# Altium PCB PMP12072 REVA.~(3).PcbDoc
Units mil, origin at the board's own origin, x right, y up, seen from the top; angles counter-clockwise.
Board outline 4950 x 3450 mil, 2 copper layers (Top Layer, Bottom Layer), stack 62 mil thick; 23 components, 0 nets, 11 pads, 0 vias.
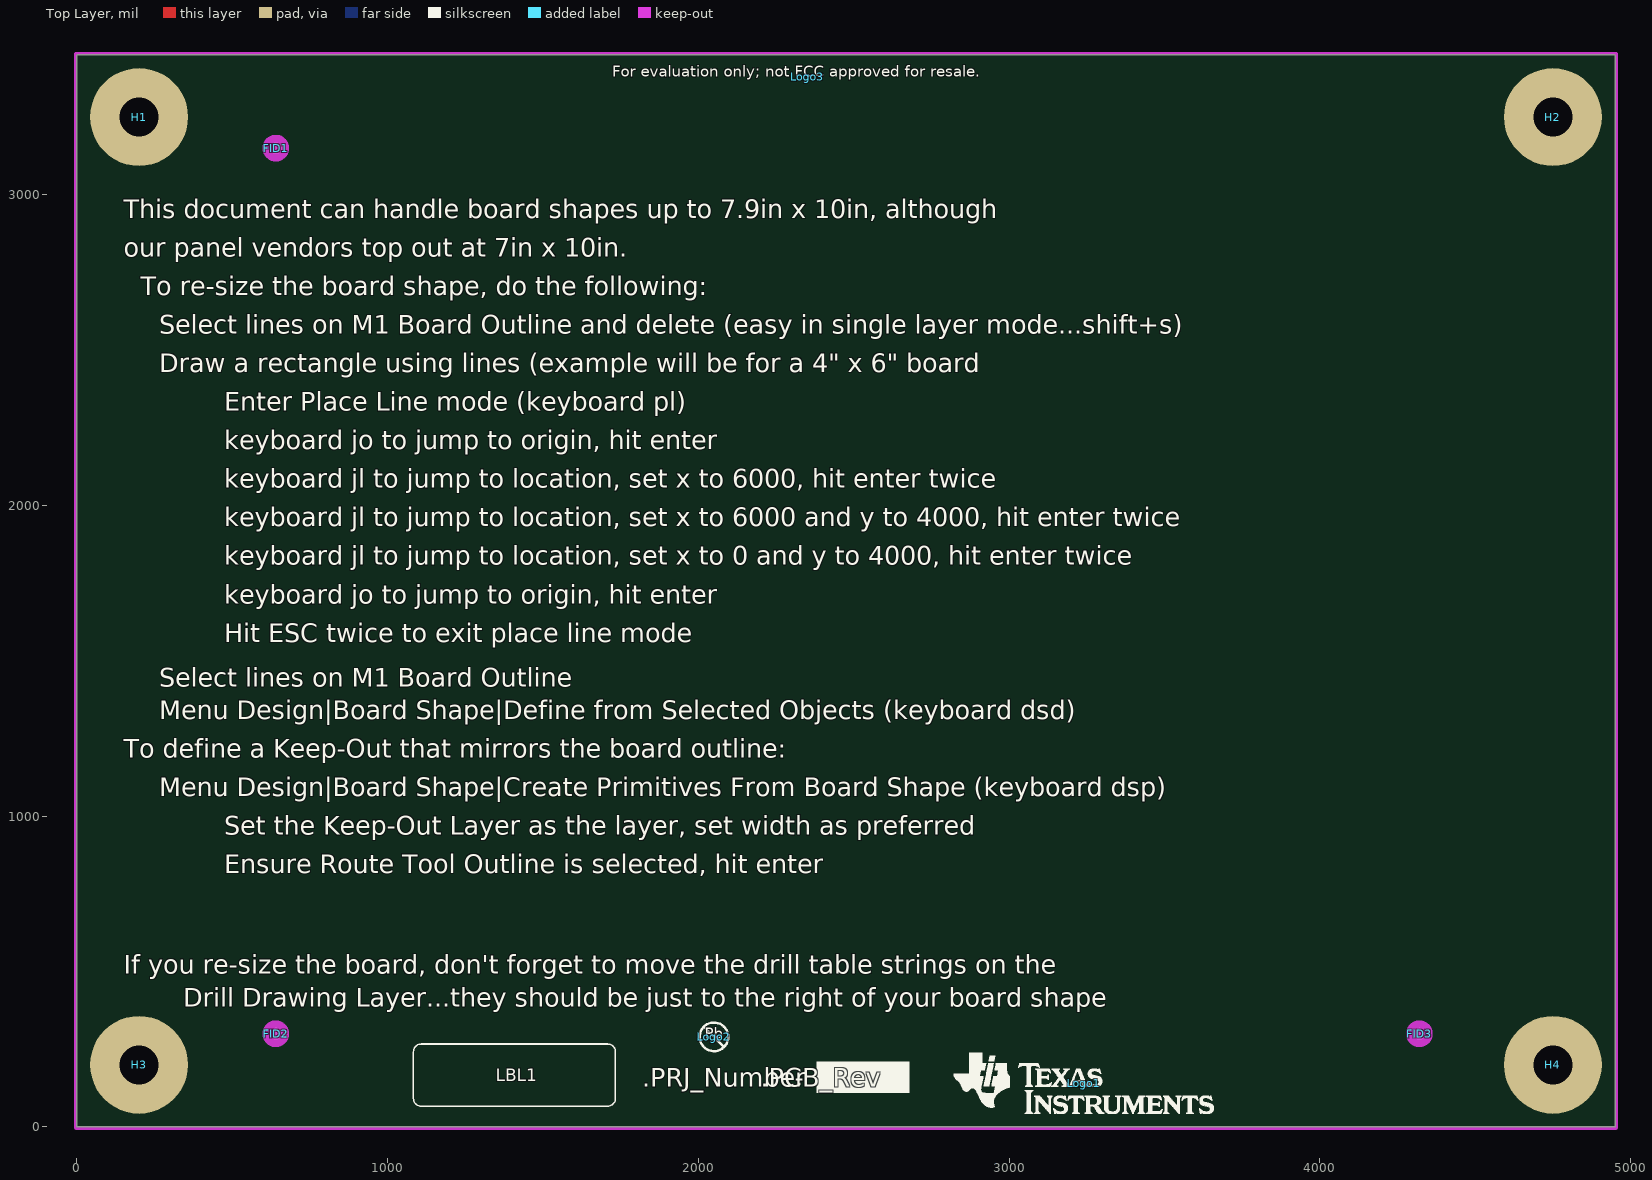
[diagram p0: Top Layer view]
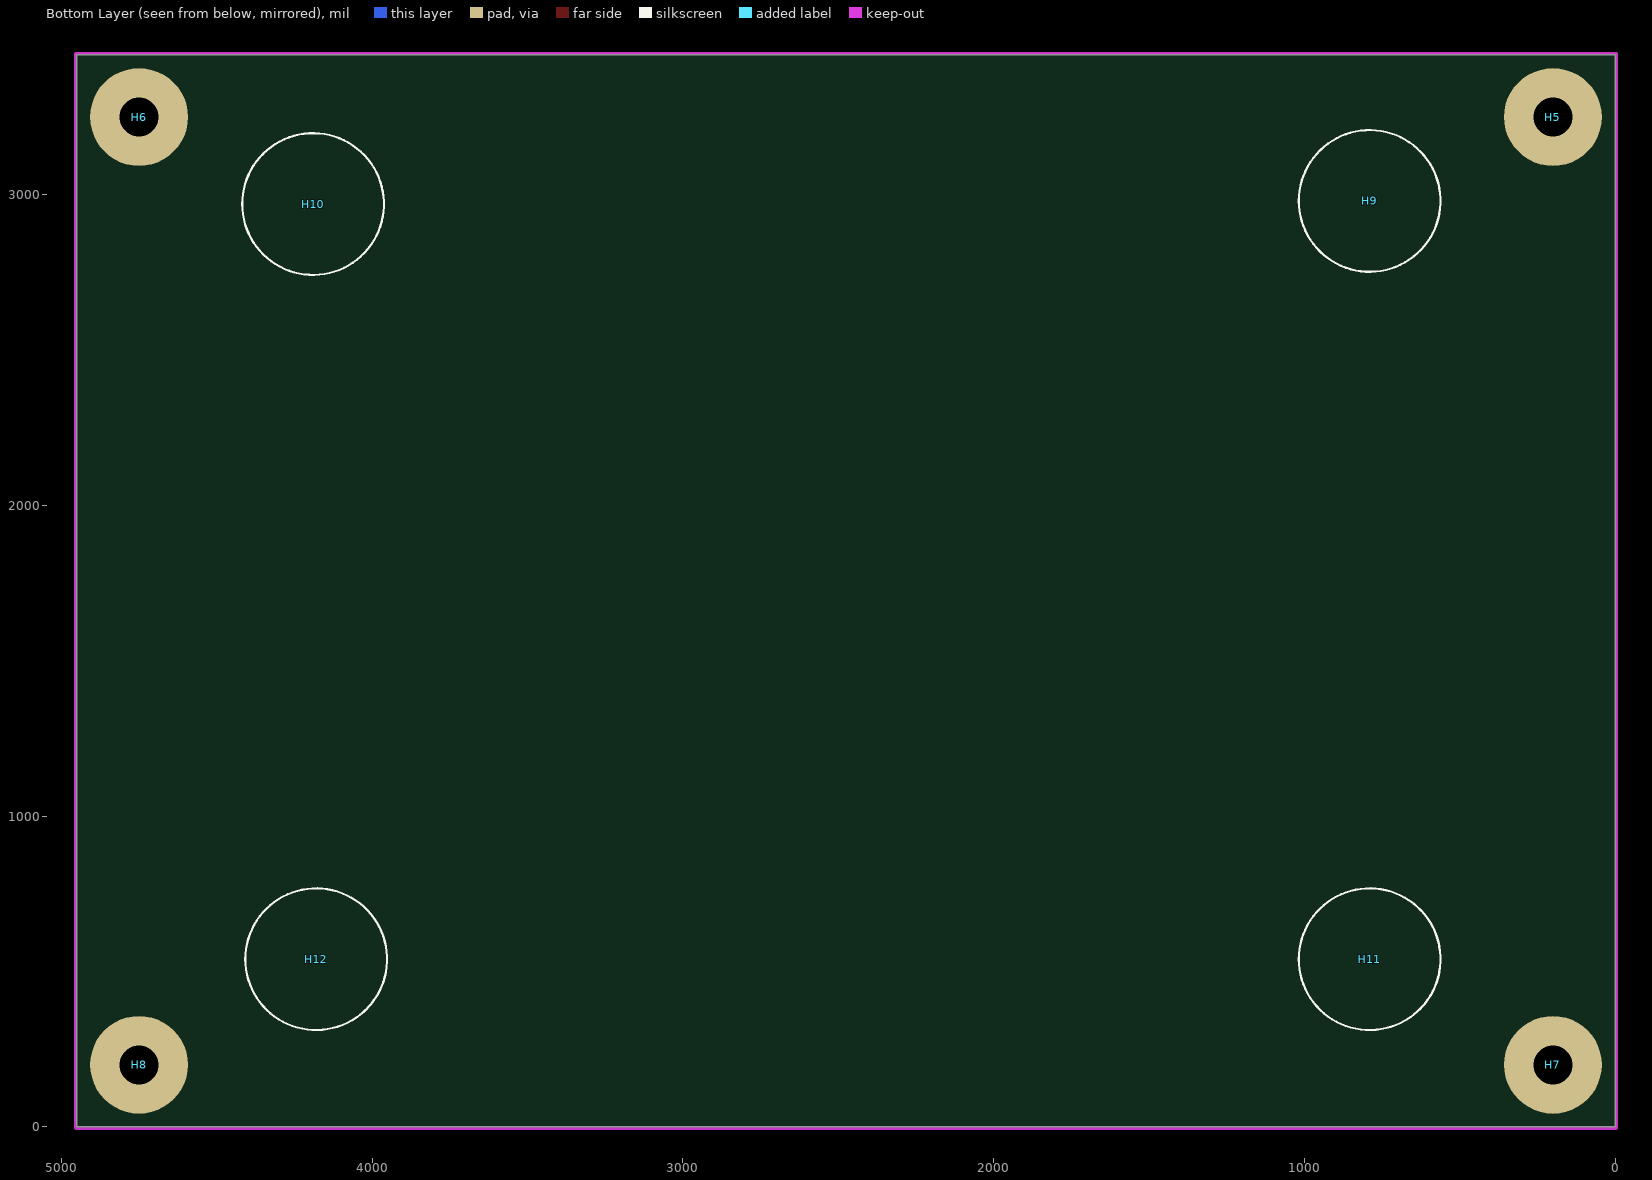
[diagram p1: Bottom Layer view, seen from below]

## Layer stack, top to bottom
Top Solder: solder mask 0.4, Solder Resist, Dk 3.5
Top Layer: signal copper 1.4
Dielectric1: core 59.2, FR-4, Dk 4.8
Bottom Layer: signal copper 1.4
Bottom Solder: solder mask 0.4, Solder Resist, Dk 3.5

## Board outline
0,0 4950,0 4950,3450 0,3450

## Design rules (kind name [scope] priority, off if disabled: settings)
AcuteAngle [All] p1: minimum=4.50000000000000E+0001 checktracksonly=FALSE
AssemblyTestPointUsage [All] p1: valid=2
Clearance Clearance_Keepouts [((IsTrack Or IsArc) And Not InPoly) And IsFree and IsKeepOut vs ((IsTrack Or IsArc) And Not InPoly) And IsFree and IsKeepOut] p1: gap=0
Clearance Clearance_BoardEdge_MountingHoles [OnCopper and InComponentClass('Mounting Holes') vs IsKeepOut] p2: gap=40
Clearance Clearance_BoardEdge_Poly [OnCopper and InPoly vs IsKeepOut] p3: gap=25
Clearance Clearance_BoardEdge [OnCopper and Not InComponentClass('Logo') and not InComponentClass('FiducialMark') and not InRegion(1000,500,4000,800) and Not IsKeepout vs IsKeepOut] p4: gap=75
Clearance Clearance_Poly [InPolygon] p5: gap=25
Clearance [All] p6: gap=7.87
ComponentClearance ComponentClearance_MountingHoles_FiducialMarks [InComponentClass('Mounting Holes') vs InComponentClass('FiducialMark')] p1: gap=50 collisioncheckmode=3 verticalgap=10 showdistances=FALSE
ComponentClearance ComponentClearance_Shunt [InComponentClass('Header') vs InComponentClass('Shunt')] p2: gap=0 collisioncheckmode=3 verticalgap=0 showdistances=FALSE
ComponentClearance ComponentClearance_Logo [InComponentClass('Logo')] p3: gap=50 collisioncheckmode=3 verticalgap=10 showdistances=FALSE
ComponentClearance ComponentClearance_ScrewToNut [(HasFootprint('NY PMS 440 0025 PH')) vs (HasFootprint('Keystone_1902C'))] p4: gap=5 collisioncheckmode=3 verticalgap=10 showdistances=FALSE
ComponentClearance ComponentClearance_MountingHoles [InComponentClass('Mounting Holes')] p5: gap=250 collisioncheckmode=3 verticalgap=100000 showdistances=FALSE
ComponentClearance ComponentClearance_SmallPassives [HasFootprint('0201*') or HasFootprint('0402*') or HasFootprint('0508') or HasFootprint('0603*') or HasFootprint('0612') or HasFootprint('0805*') or HasFootprint('0815*') or HasFootprint('0830*') or HasFootprint('1206*') or HasFootprint('1210*') or HasFootprint('1808*') or HasFootprint('1812*') or HasFootprint('1825*') or HasFootprint('2010*') or HasFootprint('2220*') or HasFootprint('2225*') or HasFootprint('2512*') or HasFootprint('2728*') or HasFootprint('3518*') vs HasFootprint('0201*') or HasFootprint('0402*') or HasFootprint('0508') or HasFootprint('0603*') or HasFootprint('0612') or HasFootprint('0805*') or HasFootprint('0815*') or HasFootprint('0830*') or HasFootprint('1206*') or HasFootprint('1210*') or HasFootprint('1808*') or HasFootprint('1812*') or HasFootprint('1825*') or HasFootprint('2010*') or HasFootprint('2220*') or HasFootprint('2225*') or HasFootprint('2512*') or HasFootprint('2728*') or HasFootprint('3518*')] p6: gap=20 collisioncheckmode=3 verticalgap=10 showdistances=FALSE
ComponentClearance ComponentClearance_THtoSMT [IsThruComponent vs IsSMTComponent] p7: gap=100 collisioncheckmode=3 verticalgap=30 showdistances=FALSE
ComponentClearance ComponentClearance_THtoTH [IsThruComponent vs IsThruComponent] p8: gap=118.11 collisioncheckmode=3 verticalgap=30 showdistances=FALSE
ComponentClearance [All] p9: gap=40 collisioncheckmode=3 verticalgap=10 showdistances=FALSE
DiffPairsRouting [All] p1: maxlimit=100 minlimit=10 mostfreqgap=10 toplayer_minwidth=15 toplayer_maxwidth=15 toplayer_prefwidth=15 bottomlayer_minwidth=15 bottomlayer_maxwidth=15 bottomlayer_prefwidth=15 maxuncoupledlength=1000
FabricationTestPointUsage TestPointUsage [All] p1: valid=2 allowmultiple=FALSE
FabricationTestpoint Testpoint [All] p1: side=3 testpointundercomponent=TRUE minsize=40 maxsize=100 preferedsize=60 minholesize=0 maxholesize=40 preferedholesize=32 testpointgrid=1 allowsidetop=TRUE allowsidebottom=TRUE usegrid=TRUE gridtolerance=0.01
FanoutControl Fanout_LCC [IsLCC] p1: bgadir=Out bgaviamode=Centered fanoutstyle=Auto fanoutdirection=Alternating viagrid=1 // Fanout_LCC (Default Rule)
FanoutControl Fanout_BGA [IsBGA] p2: bgadir=Out bgaviamode=Centered fanoutstyle=Auto fanoutdirection=Alternating viagrid=1 // Fanout_BGA (Default Rule)
FanoutControl Fanout_Default [All] p4: bgadir=Out bgaviamode=Centered fanoutstyle=Auto fanoutdirection=Alternating viagrid=1 // Fanout_Default (Default Rule)
FanoutControl Fanout_Small [(CompPinCount < 5)] p5: bgadir=Out bgaviamode=Centered fanoutstyle=Auto fanoutdirection=OutThenIn viagrid=1 // Fanout_Small (Default Rule)
HoleSize [All] p1: absolutevalues=TRUE maxlimit=251 minlimit=8 maxpercent=80.000 minpercent=20.000
MinimumAnnularRing MinimumAnnularRing_ThermalPadVias [IsVia and InAnyComponent] p1: minimumring=5.91
MinimumAnnularRing [All] p2: minimumring=9
MinimumSolderMaskSliver MinimumSolderMaskSliver_Logo [InComponentClass('Logo') vs InComponentClass('Logo')] p1: minsoldermaskwidth=0.7
MinimumSolderMaskSliver [All] p2: minsoldermaskwidth=3.94
PlaneConnect [All] p1: planeconnectstyle=Relief reliefexpansion=10 reliefentries=4 reliefconductorwidth=10 reliefairgap=10
PolygonConnect [All] p1: connectstyle=Relief reliefconductorwidth=10 reliefentries=4 polygonreliefangle="90 Angle" airgapwidth=10
RoutingVias ThermalPadVias [IsVia and InAnyComponent] p1: holewidth=7.87 width=19.68 viastyle="Through Hole" minholewidth=7.87 minwidth=19.68 maxholewidth=12.99 maxwidth=23.62
RoutingVias [All] p2: holewidth=16 width=34 viastyle="Through Hole" minholewidth=7.87 minwidth=26 maxholewidth=40 maxwidth=65
SilkToBoardRegionClearance [Not ((IsComment or IsDesignator) And (Hide <> 'False')) and not InRegion(1000,500,4000,800)] p1:
SilkToSilkClearance SilkToSilkClearance_Pb-FreeLogo [(HasFootprint('Pb-Free_Overlay_Medium') OR HasFootprint('Pb-Free_Overlay_Small')) vs (HasFootprint('Pb-Free_Overlay_Medium') OR HasFootprint('Pb-Free_Overlay_Small'))] p1: silktosilkclearance=0
SilkToSilkClearance [All] p2: silktosilkclearance=4
SilkToSolderMaskClearance SilkToComonentPadClearance [IsPad and InAnycomponent] p1: minsilkscreentomaskgap=5 clearancetoexposedcopper=TRUE
SilkToSolderMaskClearance "Silk to Solder Mask Opening" [All] p2: minsilkscreentomaskgap=4 clearancetoexposedcopper=FALSE
SolderMaskExpansion [All] p1: expansion=1.97
UnpouredPolygon [All] p1: allowunpoured=FALSE
Width [All] p1: maxlimit=100 minlimit=6 preferedwidth=10 checkconnectedcopper=TRUE
14 further rules are at their usual default settings.

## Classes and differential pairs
component class Label: LBL1
component class AssemblyNote: ZZ1 ZZ2 ZZ3 ZZ4
component class FiducialMark: FID1 FID2 FID3
component class Logo: Logo1
component class "Mounting Holes": H1 H2 H3 H4

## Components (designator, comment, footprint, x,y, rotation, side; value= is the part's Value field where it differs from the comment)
FID1 "Fiducial" Fiducial10-20 640,3150 r0 top
FID2 "Fiducial" Fiducial10-20 640,300 r0 top
FID3 "Fiducial" Fiducial10-20 4320,300 r0 top
H1 "NY PMS 440 0025 PH" "NY PMS 440 0025 PH" 200,3250 r0 top locked
H2 "NY PMS 440 0025 PH" "NY PMS 440 0025 PH" 4750,3250 r0 top locked
H3 "NY PMS 440 0025 PH" "NY PMS 440 0025 PH" 200,200 r0 top locked
H4 "NY PMS 440 0025 PH" "NY PMS 440 0025 PH" 4750,200 r0 top locked
H5 "1902C" Keystone_1902C 200,3250 r180 bottom locked
H6 "1902C" Keystone_1902C 4750,3250 r180 bottom locked
H7 "1902C" Keystone_1902C 200,200 r180 bottom locked
H8 "1902C" Keystone_1902C 4750,200 r180 bottom locked
H9 "SJ-5303 (CLEAR)" Bumpon_SJ5003Transparent 790,2980 r180 bottom
H10 "SJ-5303 (CLEAR)" Bumpon_SJ5003Transparent 4190,2970 r180 bottom
H11 "SJ-5303 (CLEAR)" Bumpon_SJ5003Transparent 790,540 r180 bottom
H12 "SJ-5303 (CLEAR)" Bumpon_SJ5003Transparent 4180,540 r180 bottom
LBL1 "Size: 0.65\" x 0.20 \"" Label_650x200 1408,167 r0 top
Logo1 "Texas Instruments" TI_Stacked_Overlay_Small 3240,140 r0 top
Logo2 "Pb-Free Symbol" Pb-Free_Overlay_Small 2050,290 r0 top
Logo3 "FCC disclaimer" FCC_disclaimer 2350,3380 r0 top
ZZ1 "This Assembly Note is for PCB labels only" AssemblyNoteLabel 185,3938 r0 top
ZZ2 "These assemblies are ESD sensitive, ESD precautions shall be observed." AssemblyNote 185,3829.11 r0 top
ZZ3 "These assemblies must be clean and free from flux and all contaminants. Use of no clean flux is not acceptable." AssemblyNote 185,3740.56 r0 top
ZZ4 "These assemblies must comply with workmanship standards IPC-A-610 Class 2, unless otherwise specified." AssemblyNote 185,3652 r0 top

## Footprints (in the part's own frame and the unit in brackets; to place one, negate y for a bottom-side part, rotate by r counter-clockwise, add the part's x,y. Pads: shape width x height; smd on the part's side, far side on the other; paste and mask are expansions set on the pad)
AssemblyNote [mil] "Assembly Note"
AssemblyNoteLabel [mil] "Assembly Note for PCB Labels"
Bumpon_SJ5003Transparent [mil] "3M Hemispherical Bumpon transparent"
  round 1 on Mech4: 0(0,0)
  silkscreen extent -228,-228 228,228, body extent -217,-218 219,218, height 197
FCC_disclaimer [mil]
Fiducial10-20 [mm]
  round 1 smd mask+0.5: 1(0,0)
  Top Layer keep-out circle w1.178: c0,0 r0.5
Keystone_1902C [mil] "Hex Standoff, 4-40 threaded, nylon"
  body extent -145,-126 146,126, height 501
Label_650x200 [mil] "Thermal Transfer Label"
  silkscreen extent -325,-100 325,100, body extent -326,-101 326,101, height 1
"NY PMS 440 0025 PH" [mm] "4-40 nylon screw and mounting hole"
  round 8 hole 3.2: 1(0,0)
  body extent -3.3,-3.3 3.3,3.3, height 2.69
Pb-Free_Overlay_Small [mil]
  silkscreen extent -46,-46 46,46
TI_Stacked_Overlay_Small [mil]
  silkscreen extent -418,-98 418,98

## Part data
FID1 FID2 FID3: "Fiducial mark.  There is nothing to buy or mount."
H1 H2 H3 H4: "Machine Screw, Round, #4-40 x 1/4, Nylon, Philips panhead"
H5 H6 H7 H8: "Standoff, Hex, 0.5\"L #4-40 Nylon"
H9 H10 H11 H12: "Bumpon, Hemisphere, 0.44 X 0.20, Clear"
LBL1: library part THT-14-423-10, "Thermal Transfer Printable Labels, 0.650\" W x 0.200\" H - 10,000 per roll"
Logo1: library part TI_Logo, "Texas Instrument Corporate Signature"
Logo2: library part Pb-Free
Logo3: library part FCC_disclaimer, "FCC_disclaimer"
ZZ1: library part AssemblyNoteLabel
ZZ2 ZZ3 ZZ4: library part AssemblyNote

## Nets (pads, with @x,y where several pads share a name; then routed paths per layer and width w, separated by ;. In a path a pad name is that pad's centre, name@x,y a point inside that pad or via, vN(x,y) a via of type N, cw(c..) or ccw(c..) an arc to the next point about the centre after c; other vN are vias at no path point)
pads on no net: FID1.1 FID2.1 FID3.1 H1.1 H2.1 H3.1 H4.1 H9.0 H10.0 H11.0 H12.0

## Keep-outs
Keep-Out Layer:
  lines w10: -5,0 ccw(c0,0) 0,-5 ; -5,0 ccw(c0,0) 0,-5 ; -5,0 -5,3450 ; -5,3450 cw(c0,3450) 0,3455 ; -5,3450 cw(c0,3450) 0,3455 ; 0,-5 4950,-5 ; 0,3455 4950,3455 ; 4950,-5 ccw(c4950,0) 4955,0 ; 4950,-5 ccw(c4950,0) 4955,0 ; 4950,3455 cw(c4950,3450) 4955,3450 ; 4950,3455 cw(c4950,3450) 4955,3450 ; 4955,0 4955,3450
  text ".Layer_Name" at 577,-858.49 h60

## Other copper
Top Layer:
  text ".Layer_Name" at 577,-858.49 h60
Bottom Layer:
  text ".Layer_Name" at 577,-858.49 h60

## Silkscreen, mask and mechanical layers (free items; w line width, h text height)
Top Overlay:
  region: 2680,210 2380,210 2380,110 2680,110
  text "This document can handle board shapes up to 7.9in x 10in, although" at 150,2925 h60
  text "our panel vendors top out at 7in x 10in." at 150,2800.94 h60
  text "To re-size the board shape, do the following:" at 205,2676.88 h60
  text "Select lines on M1 Board Outline and delete (easy in single layer mode...shift+s)" at 265,2552.82 h60
  text "Draw a rectangle using lines (example will be for a 4\" x 6\" board" at 265,2428.76 h60
  text "Enter Place Line mode (keyboard pl)" at 475,2304.71 h60
  text "keyboard jo to jump to origin, hit enter" at 475,2180.65 h60
  text "keyboard jl to jump to location, set x to 6000, hit enter twice" at 475,2056.59 h60
  text "keyboard jl to jump to location, set x to 6000 and y to 4000, hit enter twice" at 475,1932.53 h60
  text "keyboard jl to jump to location, set x to 0 and y to 4000, hit enter twice" at 475,1808.47 h60
  text "keyboard jo to jump to origin, hit enter" at 475,1684.41 h60
  text "Hit ESC twice to exit place line mode" at 475,1560.35 h60
  text "Select lines on M1 Board Outline" at 265,1416.3 h60
  text "Menu Design|Board Shape|Define from Selected Objects (keyboard dsd)" at 265,1312.24 h60
  text "To define a Keep-Out that mirrors the board outline:" at 150,1188.18 h60
  text "Menu Design|Board Shape|Create Primitives From Board Shape (keyboard dsp)" at 265,1064.12 h60
  text "Set the Keep-Out Layer as the layer, set width as preferred" at 475,940.06 h60
  text "Ensure Route Tool Outline is selected, hit enter" at 475,816 h60
  text "If you re-size the board, don't forget to move the drill table strings on the" at 150,493 h60
  text "Drill Drawing Layer...they should be just to the right of your board shape" at 343,387 h60
  text ".PRJ_Number" at 1820,130.01 h60
  text ".PCB_Rev" at 2200,130.01 h60
  text "-" at 2310,130.01 h60
  text ".Layer_Name" at 577,-858.49 h60
Bottom Overlay:
  text ".Layer_Name" at 577,-858.49 h60
Top Paste:
  text ".Layer_Name" at 577,-858.49 h60
Bottom Paste:
  text ".Layer_Name" at 577,-858.49 h60
Top Solder:
  text ".Layer_Name" at 577,-858.49 h60
  text ".Layer_Name" at 577,-858.49 h60
Bottom Solder:
  text ".Layer_Name" at 577,-858.49 h60
Drill Guide:
  text ".Layer_Name" at 577,-858.49 h60
M1 Board Outline:
  the board outline again, w10
  text ".Layer_Name" at 577,-858.49 h60
M2 Board Dimensions:
  rectangle: 125,-400 500,-275
  rectangle: 0,-275 125,-150
  lines w7: 0,-275 1000,-275 ; 125,-400 125,-150 ; 250,-400 250,-150 ; 500,-400 500,-150 ; 750,-400 750,-150 ; 0,-400 0,-150 1000,-150 1000,-400 0,-400
  text ".Layer_Name" at 577,-858.49 h60
M3 3D STEP Top:
  text ".Layer_Name" at 577,-858.49 h60
M4 3D STEP Bottom:
  text ".Layer_Name" at 577,-858.49 h60
M5 Assembly Top:
  lines w10: -292,-930.17 6308,-930.17 ; -292,-726.83 6310,-726.83 ; -292,-523.5 -292,-1133.5 3713,-1133.5 6310,-1133.5 6310,-523.5 -291.5,-523.5 -291.5,-1133.5 1284,-1133.5 ; 2173,-1133.5 2173,-523.5 ; 3440,-726.83 3440,-523.5 ; 4280,-726.83 4280,-523.5 ; 4902,-1140 4902,-937.17
  text "COMPONENTS MARKED 'DNP' SHOULD NOT BE POPULATED." at 1153.5,-318.5 h60
  text "ASSEMBLY VARIANT:" at 1153,-434 h60
  text ".VariantName" at 2189,-434 h60
  text "PCB VIEWED FROM TOP SIDE" at -228.5,-655.67 h60
  text "BOARD #:" at 2248,-655.67 h60
  text ".PRJ_Number" at 2793.5,-655.67 h60
  text "REV:" at 3638,-655.67 h60
  text ".PCB_Rev" at 3929.5,-655.67 h60
  text "SVN REV:" at 4476,-655.67 h60
  text ".VersionControl_RevNumber" at 4982,-655.67 h60
  text "TID #:" at 2248,-859 h60
  text ".TID" at 2793.5,-859 h60
  text "PLOT NAME =" at -228.5,-1064.34 h60
  text ".plot_File_Name" at 577,-1064.34 h60
  text "GENERATED    :" at 2250,-1064.34 h60
  text ".Print_Date" at 3119.5,-1064.34 h60
  text ".Print_Time" at 3848.5,-1064.34 h60
  text "TEXAS INSTRUMENTS" at 5113,-1064.34 h60
M6 Assembly Bottom:
  lines w10: -292.5,-727.33 6309.5,-727.33 ; -290.5,-930.67 6309.5,-930.67 ; 1115.5,-1140.5 1115.5,-937.67 ; 1737.5,-727.33 1737.5,-524 ; 2577.5,-727.33 2577.5,-524 ; 3844.5,-1134 3844.5,-524 ; 4733.5,-1134 6309,-1134 6309,-524 -292.5,-524 -292.5,-1134 2304.5,-1134 6309.5,-1134 6309.5,-524
  text "COMPONENTS MARKED 'DNP' SHOULD NOT BE POPULATED." at 6102,-318 h60
  text ".VariantName" at 5058,-434 h60
  text "ASSEMBLY VARIANT:" at 6097,-434 h60
  text ".VersionControl_RevNumber" at 1035.5,-656.17 h60
  text "SVN REV:" at 1541.5,-656.17 h60
  text ".PCB_Rev" at 2088,-656.17 h60
  text "REV:" at 2379.5,-656.17 h60
  text ".PRJ_Number" at 3224,-656.17 h60
  text "BOARD #:" at 3769.5,-656.17 h60
  text "PCB VIEWED FROM BOTTOM SIDE" at 6246,-656.17 h60
  text ".TID" at 3224,-859.5 h60
  text "TID #:" at 3769.5,-859.5 h60
  text "TEXAS INSTRUMENTS" at 904.5,-1064.84 h60
  text ".Print_Time" at 2169,-1064.84 h60
  text ".Print_Date" at 2898,-1064.84 h60
  text "GENERATED    :" at 3767.5,-1064.84 h60
  text ".plot_File_Name" at 5440.5,-1064.84 h60
  text "PLOT NAME =" at 6246,-1064.84 h60
M9 Title Sheet:
  drawing of 57 lines, arcs and shapes, not listed
  text "1" at 739.84,8036.5 h70
  text "2" at 3235.5,8036.5 h70
  text "3" at 5724.84,8036.5 h70
  text "4" at 8231.51,8036.5 h70
  text "5" at 10730.5,8036.5 h70
  text "6" at 13235.5,8036.5 h70
  text "A" at -416.5,6893.5 h70
  text "A" at 14383.5,6893.5 h70
  text "B" at -416.5,4513.5 h70
  text "B" at 14383.5,4513.5 h70
  text "C" at -416.5,2138.5 h70
  text "C" at 14383.5,2138.5 h70
  text "PROJECT TITLE:" at 11343.5,277.5 h45
  text ".PRJ_Title" at 11393.5,144.17 h70
  text "DESIGNED FOR:" at 11343.5,-23.5 h45
  text ".PRJ_Customer" at 11393.5,-163.5 h70
  text "D" at -416.5,-231.5 h70
  text "D" at 14383.5,-231.5 h70
  text "FILE NAME:" at 11343.5,-323.5 h45
  text ".PCB_File_Name_No_Path" at 11393.5,-443.5 h70
  text "Texas Instruments (TI) and/or its licensors do not warrant the accuracy or completeness of this specification" at 6374,-605.34 h45
  text "ENGINEER:" at 11343.5,-613.5 h45
  text "LAYOUT BY:" at 12848.5,-613.5 h45
  text "or any information contained therein. TI and/or its licensors do not warrant that this design will meet" at 6329.01,-718 h45
  text ".PRJ_Engineer" at 11393.5,-768.49 h70
  text ".PCB_Layout" at 12899,-768.49 h70
  text "the specifications, will be suitable for your application or fit for any particular purpose, or will operate in" at 6329.01,-830.67 h45
  text ".Layer_Name" at 577,-858.49 h60
  text "ALTIUM DESIGNER VERSION:" at 12848.5,-923.5 h45
  text "an implementation. TI and/or its licensors do not warrant that the design is production worthy. You should" at 6329.01,-943.33 h45
  text "completely validate and test your design implementation to confirm the system functionality for your application." at 6374,-1056 h45
  text ".print_Scale" at 11393.5,-1056.83 h70
  text ".Application_BuildNumber" at 12899,-1056.83 h70
  text "1" at 739.84,-1263.5 h70
  text "2" at 3235.5,-1263.5 h70
  text "3" at 5724.84,-1263.5 h70
  text "4" at 8231.51,-1263.5 h70
  text "5" at 10730.5,-1263.5 h70
  text "6" at 13235.5,-1263.5 h70
M10 Fab Notes:
  drawing of 173 lines, arcs and shapes, not listed
  text "DESIGN INFORMATION" at 12377.02,6201 h60
  text "MIN. TRACK WIDTH:" at 11732.46,6021 h60
  text "8" at 12828.7,6021 h60
  text "MIL" at 12983.46,6021 h60
  text "MIN. CLEARANCE:" at 11732.46,5889 h60
  text "0.2" at 12768.7,5889 h60
  text "mm" at 12983.46,5889 h60
  text "MIN. VIA PAD SIZE:" at 11732.46,5757 h60
  text "24" at 12798.71,5757 h60
  text "MIL" at 12983.46,5757 h60
  text "0.05mm (2MIL)" at 12427.46,5615.29 h60
  text "MINIMUM ANNULAR RING" at 11403.23,5611 h60
  text "EXTERNAL" at 13135.46,5611 h60
  text "PER" at 11603.23,5493 h60
  text "IPC-D-275 CLASS 2 LEVEL C" at 11823.23,5493 h60
  text "MIL, HOLES" at 13311.46,5380.71 h60
  text "+/-" at 12919,5380 h60
  text "+/-" at 13773,5380 h60
  text "REGISTRATION TOLERANCES:" at 11403.23,5375 h60
  text "METAL" at 12603,5375 h60
  text "5" at 13179.2,5375 h60
  text "3" at 14012.2,5375 h60
  text "MIL" at 14128.46,5375 h60
  text "+/-" at 13773,5262 h60
  text "HOLE SIZE TOLERANCE (UNLESS OTHERWISE SPECIFIED):" at 11403.23,5257 h60
  text "3" at 14012.2,5257 h60
  text "MIL" at 14128.46,5257 h60
  text "MATERIAL:" at 11328.46,5047.54 h60
  text "FR-4 High Tg" at 12314.9,4907.21 h60
  text "FR-408" at 11749.46,4898.64 h60
  text "OTHER" at 13237.46,4898.64 h60
  text "X" at 12160,4895 h60
  text "62 MIL (1.6mm) +/-10%" at 12069.56,4735.92 h60
  text "THICKNESS:" at 11403.23,4731.64 h60
  text "X" at 11941.4,4731.64 h60
  text "OTHER" at 13354.46,4731.64 h60
  text "TOLERANCE:" at 11403.23,4573.64 h60
  text "X" at 12242.53,4573.64 h60
  text "ANSI IPC-6012 TYPE 3 CLASS 2" at 12429.48,4573.64 h60
  text "OTHER +/-" at 12429.46,4417.64 h60
  text "BOW & TWIST:" at 11403.23,4260.64 h60
  text "X" at 12242.53,4260.64 h60
  text "ANSI IPC-6012 TYPE 3 CLASS 2" at 12429.48,4260.64 h60
  text "OTHER +/-" at 12429.46,4102.13 h60
  text "DRILLING:" at 11328.46,3963.64 h60
  text "REFERENCE:" at 11403.23,3846.64 h60
  text "X" at 12051.46,3846.64 h60
  text "AS SHOWN" at 12238.46,3846.64 h60
  text "X" at 12952.46,3846.64 h60
  text "NC_DRILL FILES" at 13089.46,3846.64 h60
  text "PTH MIN COPPER THICKNESS:" at 11403.23,3688.64 h60
  text "X" at 12753.46,3688.64 h60
  text "1MIL" at 12890.46,3688.64 h60
  text "OTHER" at 13387.46,3688.64 h60
  text "BOARD FINISH:" at 11328.46,3529.64 h60
  text "SILKSCREEN:" at 11483.68,3411.64 h60
  text "X" at 12432.46,3411.64 h60
  text "TOP" at 12558.46,3411.64 h60
  text "X" at 12942.46,3411.64 h60
  text "BOTTOM" at 13069.46,3411.64 h60
  text "SILKSCREEN COLOR:" at 11483.68,3244.64 h60
  text "X" at 12431.42,3244.64 h60
  text "WHITE" at 12558.46,3244.64 h60
  text "OTHER" at 13069.46,3244.64 h60
  text "X" at 12562.42,3085.44 h60
  text "GREEN" at 12689.46,3085.44 h60
  text "OTHER" at 13307.46,3085.44 h60
  text "SOLDER RESIST COLOR:" at 11483.68,3074.64 h60
  text "X" at 12562.42,2915.44 h60
  text "MATTE" at 12689.46,2915.44 h60
  text "SEMI-GLOSS" at 13307,2914.8 h60
  text "IMMERSION GOLD (ENIG)" at 12389.46,2726.92 h60
  text "ENEPIG" at 13727,2723.64 h60
  text "SURFACE FINISH:" at 11328.46,2722.64 h60
  text "X" at 12202.51,2722.64 h60
  text "IMM. TIN/SILVER OR EQUIV" at 11658,2565.64 h60
  text "OTHER" at 13089.46,2565.64 h60
  text "ARRAY/PANEL:" at 11328.46,2386.64 h60
  text "CUT AND TRIM PER M1 BOARD OUTLINE" at 12389.46,2382.35 h60
  text "N.C. ROUTE" at 12389.46,2230.64 h60
  text "X" at 13068.46,2230.64 h60
  text "V. SCORE" at 13255.46,2230.64 h60
  text "CERTIFICATION:" at 11328.46,2093.64 h60
  text "MATERIALS AND WORKMANSHIP FOR ALL PCBS" at 12053.46,2093.64 h60
  text "TO MEET OR EXCEED THE REQUIREMENTS OF:" at 12053.46,1995.64 h60
  text "X" at 11679.96,1859.13 h60
  text "ANSI IPC-A-600F CLASS ->" at 11818.96,1859.13 h60
  text "X" at 13458.02,1859.13 h60
  text "2" at 13576.96,1859.14 h60
  text "1" at 13261.96,1857.64 h60
  text "3" at 13930.96,1857.64 h60
  text "X" at 12494.02,1699.64 h60
  text "RoHS" at 12630.96,1699.64 h60
  text "OTHER" at 13275.36,1699.64 h60
  text "PER ORDER" at 13672.42,1699.64 h60
  text "ALL BOARDS MUST MEET OR EXCEED UL94-V0 REQUIREMENTS." at 11356,1534 h60
  text "PCB MUST BEAR THE UL94V-0 UL REGISTERED MATERIAL ID NUMBER" at 11356,1414 h60
  text "ADDITIONAL REQUIREMENTS:" at 11328.46,1240.64 h60
  text "MICROSECTION:" at 11403.23,1125.64 h60
  text "YES" at 12308.96,1125.64 h60
  text "REQUIRED" at 13170.46,969.49 h60
  text "BARE BOARD ELEC. TEST:" at 11403.23,966.64 h60
  text "NONE" at 12708.96,966.64 h60
  text "X" at 13043.46,966.64 h60
  text "PER ORDER" at 13762.46,966.64 h60
  text ".Layer_Name" at 577,-858.49 h60
M11 Gerber Information:
  lines w10: -292,-930.17 6308,-930.17 ; -292,-726.83 6310,-726.83 ; -292,-523.5 -292,-1133.5 3713,-1133.5 6310,-1133.5 6310,-523.5 -291.5,-523.5 -291.5,-1133.5 1284,-1133.5 ; 2173,-1133.5 2173,-523.5 ; 3440,-726.83 3440,-523.5 ; 4280,-726.83 4280,-523.5 ; 4902,-1140 4902,-937.17
  text "ALL ARTWORK VIEWED FROM TOP SIDE" at -228.5,-655.67 h60
  text "BOARD #:" at 2248,-655.67 h60
  text ".PRJ_Number" at 2793.5,-655.67 h60
  text "REV:" at 3638,-655.67 h60
  text ".PCB_Rev" at 3929.5,-655.67 h60
  text "SVN REV:" at 4476,-655.67 h60
  text ".VersionControl_RevNumber" at 4982,-655.67 h60
  text "LAYER NAME =" at -228.5,-858.49 h60
  text "TID #:" at 2248,-859 h60
  text ".TID" at 2793.5,-859 h60
  text "PLOT NAME =" at -228.5,-1064.34 h60
  text ".plot_File_Name" at 577,-1064.34 h60
  text "GENERATED    :" at 2250,-1064.34 h60
  text ".Print_Date" at 3119.5,-1064.34 h60
  text ".Print_Time" at 3848.5,-1064.34 h60
  text "TEXAS INSTRUMENTS" at 5113,-1064.34 h60
M12 Stackup:
  drawing of 191 lines, arcs and shapes, not listed
  text "Layer" at 9790.34,7830 h60
  text "Name" at 10200.26,7830 h60
  text "Material" at 11130,7830 h60
  text "Thickness" at 11989.77,7830 h60
  text "Constant" at 12639.6,7830 h60
  text "Board Layer Stack" at 13209.46,7830 h60
  text "1" at 9790.34,7710 h60
  text "Top Overlay" at 10200.26,7710 h60
  text "2" at 9790.34,7590 h60
  text "Top Solder" at 10200.26,7590 h60
  text "Solder Resist" at 11130,7590 h60
  text "0.40mil" at 11989.77,7590 h60
  text "3.5" at 12639.6,7590 h60
  text "3" at 9790.34,7470 h60
  text "Top Layer" at 10200.26,7470 h60
  text "Copper" at 11130,7470 h60
  text "1.40mil" at 11989.77,7470 h60
  text "4" at 9790.34,7350 h60
  text "Dielectric1" at 10200.26,7350 h60
  text "FR-4" at 11130,7350 h60
  text "59.20mil" at 11989.77,7350 h60
  text "4.8" at 12639.6,7350 h60
  text "5" at 9790.34,7230 h60
  text "Bottom Layer" at 10200.26,7230 h60
  text "Copper" at 11130,7230 h60
  text "1.40mil" at 11989.77,7230 h60
  text "6" at 9790.34,7110 h60
  text "Bottom Solder" at 10200.26,7110 h60
  text "Solder Resist" at 11130,7110 h60
  text "0.40mil" at 11989.77,7110 h60
  text "3.5" at 12639.6,7110 h60
  text "7" at 9790.34,6990 h60
  text "Bottom Overlay" at 10200.26,6990 h60
  text ".Layer_Name" at 577,-858.49 h60
M13 Component Bodies Top:
  text ".Layer_Name" at 577,-858.49 h60
M14 Component Bodies Bottom:
  text ".Layer_Name" at 577,-858.49 h60
M15 Courtyards Top:
  text ".Layer_Name" at 577,-858.49 h60
M16 Courtyards Bottom:
  text ".Layer_Name" at 577,-858.49 h60
Drill Drawing:
  lines w1: 5667.83,3196.16 5717.6,3196.16 5717.6,3245.93 5667.83,3245.93 5667.83,3196.16
  lines w12: 5600,3151.36 7718.02,3151.36 ; 5600,3300.68 7718.02,3300.68 ; 5970.36,3002.04 5970.36,3450 ; 6327.36,3002.04 6327.36,3450 ; 6988.93,3002.04 6988.93,3450 ; 7273.07,3002.04 7273.07,3450 ; 5600,3002.04 7718.02,3002.04 7718.02,3450 5600,3450 5600,3002.04
  text "Symbol" at 5689.59,3345.48 h72
  text "Quantity" at 6015.16,3345.48 h72
  text "Finished Hole Size" at 6372.16,3345.48 h72
  text "Plated" at 7033.72,3345.48 h72
  text "Hole Type" at 7317.86,3345.48 h72
  text "4" at 6015.16,3196.16 h60
  text "125.98mil (3.200mm)" at 6372.16,3196.16 h60
  text "PTH" at 7033.72,3196.16 h60
  text "Round" at 7317.86,3196.16 h60
  text "4 Total" at 6015.16,3046.84 h60
  text ".Layer_Name" at 577,-858.49 h60

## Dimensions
0,0 to 4950,0 on M2 Board Dimensions
0,0 to 0,3450 on M2 Board Dimensions
0,-400 to 1000,-400 on M2 Board Dimensions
